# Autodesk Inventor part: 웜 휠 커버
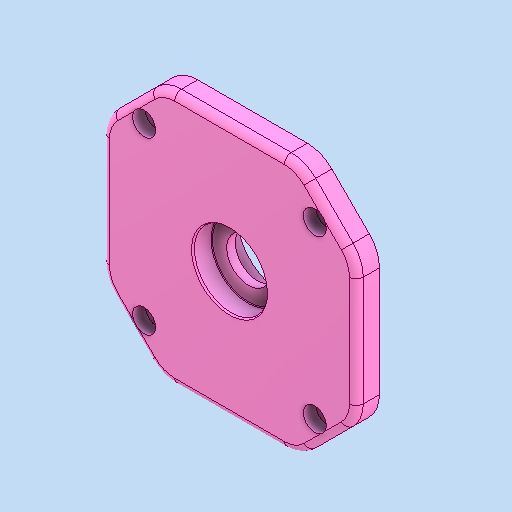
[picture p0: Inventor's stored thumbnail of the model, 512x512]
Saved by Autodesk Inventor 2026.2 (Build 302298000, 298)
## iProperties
Created: 2026-01
Part Number: 웜 휠 커버
Material: 알루미늄 6061
Document SubType Name: Modeling
Designer: PC2-07
Density: 2.7 g/cm^3
Appearance: 기본값
Author: jhkim
Sending System: Autodesk Inventor 2026
Preprocessor: ST-DEVELOPER v20.1
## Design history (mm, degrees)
feature "솔리드1"
node "솔리드2"
